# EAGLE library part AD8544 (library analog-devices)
General-Purpose CMOS Rail-to-Rail Amplifiers Source: http://www.analog.com/static/imported-files/data_sheets/AD8541_8542_8544.pdf
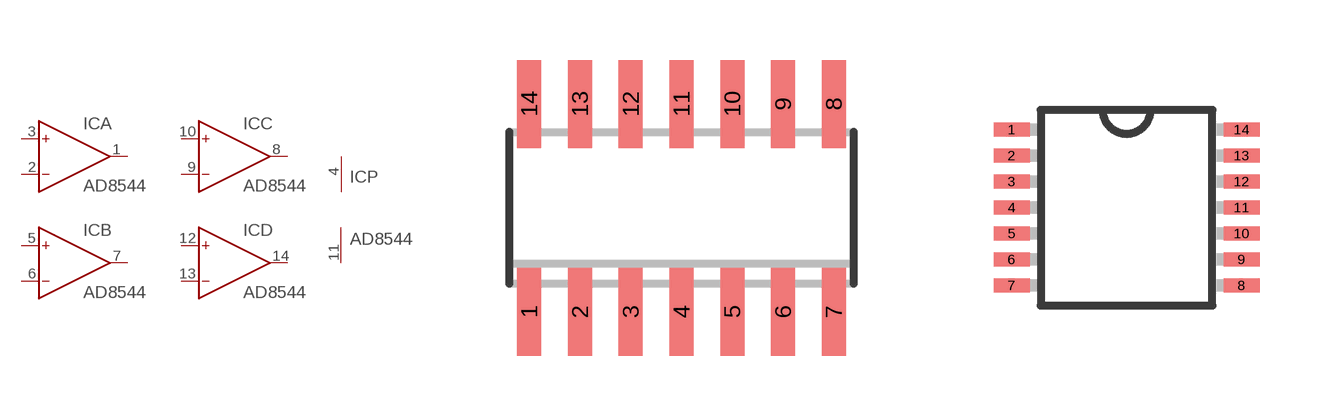
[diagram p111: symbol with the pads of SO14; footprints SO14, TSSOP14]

Designator prefix IC; gates A=OP B=OP C=OP D=OP P=PWR+-

## AD8544R (MPN: AD8544ARZ; OC_FARNELL: 9425748; OC_NEWARK: 19M0966)  [SO14]
1  A:OUT  out
2  A:IN-  in
3  A:IN+  in
4  P:V+  pwr
5  B:IN+  in
6  B:IN-  in
7  B:OUT  out
8  C:OUT  out
9  C:IN-  in
10  C:IN+  in
11  P:V-  pwr
12  D:IN+  in
13  D:IN-  in
14  D:OUT  out

## AD8544RU (MPN: AD8544ARUZ; OC_FARNELL: unknown; OC_NEWARK: 15P1001)  [TSSOP14]
Pads as for SO14

## Footprint SO14 (pad centres in mm)
14-Lead Narrow-Body SOIC (SO-14) Source: http://www.analog.com/static/imported-files/data_sheets/SSM2166.pdf
smd 0.6 x 2.2: 1 -3.81,-2.6; 2 -2.54,-2.6; 3 -1.27,-2.6; 4 0,-2.6; 5 1.27,-2.6; 6 2.54,-2.6; 7 3.81,-2.6; 8 3.81,2.6; 9 2.54,2.6; 10 1.27,2.6; 11 0,2.6; 12 -1.27,2.6; 13 -2.54,2.6; 14 -3.81,2.6

## Footprint TSSOP14 (pad centres in mm)
14-Lead Thin Shrink Small Outline Package [TSSOP] Source: Analog Devices .. 780914713ADD8704_0.pdf
smd 0.9 x 0.35: 1 -2.875,1.95; 2 -2.875,1.3; 3 -2.875,0.65; 4 -2.875,0; 5 -2.875,-0.65; 6 -2.875,-1.3; 7 -2.875,-1.95; 8 2.875,-1.95; 9 2.875,-1.3; 10 2.875,-0.65; 11 2.875,0; 12 2.875,0.65; 13 2.875,1.3; 14 2.875,1.95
